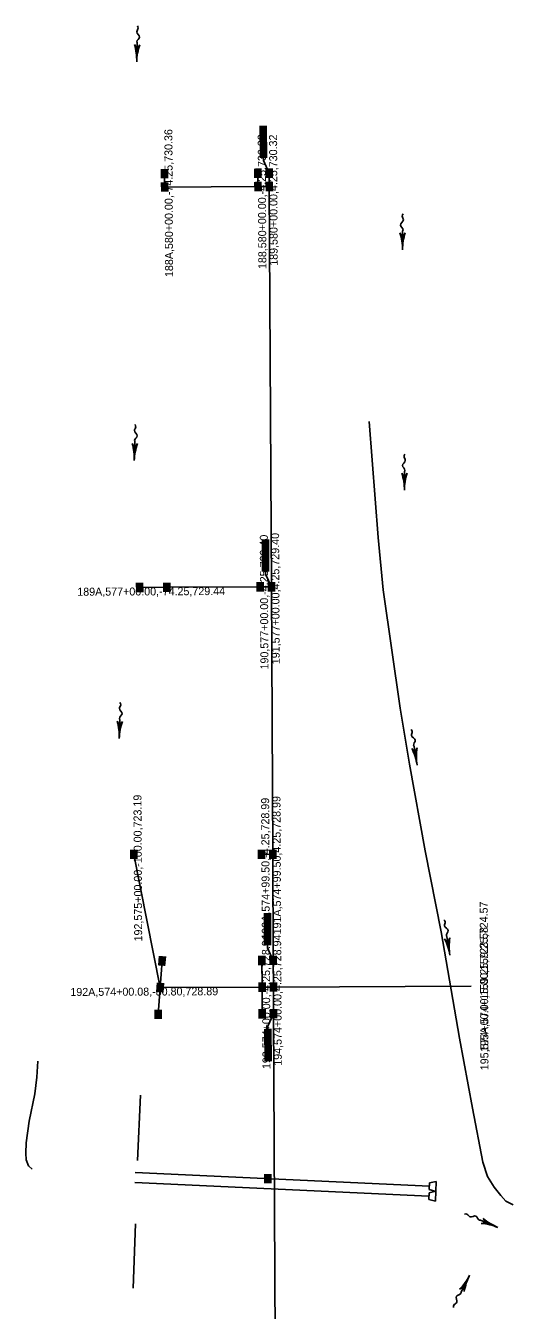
# Model space of a CAD drawing. Extents: x 593481 to 595602, y 151646 to 157396.
# Drawn here: x 594163 to 594529, y 156433 to 157396 of the extents above; entities that cross this region are included whole.
import ezdxf

# ---------------------------------------------------------------- set-up
doc = ezdxf.new("R2010")
doc.units = 0
for name, color, linetype in [('P_ALI_50_Equation', 7, 'Continuous'), ('P_DRN_Flow', 7, 'Continuous'), ('P_DRN_Inlet', 7, 'Continuous'), ('P_DRN_Pipes', 7, 'Continuous'), ('P_DRN_SS_UG', 7, 'Continuous')]:
    doc.layers.add(name, color=color, linetype=linetype)

msp = doc.modelspace()

# ---------------------------------------------------------------- linework, layer by layer
at = {"layer": 'P_DRN_Flow'}
for p, q in [((594246.42, 157368.76), (594246.88, 157382.88)), ((594445.86, 157227.78), (594445.86, 157241.9)), ((594244.64, 157069.85), (594245.1, 157083.97)), ((594447.29, 157047.54), (594447.29, 157061.66)), ((594233.34, 156861.58), (594233.8, 156875.7)), ((594456.75, 156841.63), (594454.55, 156855.59)), ((594481.36, 156699.04), (594479.17, 156713)), ((594517.39, 156495.04), (594504.34, 156500.44)), ((594496.16, 156459.25), (594489.74, 156446.66))]:
    msp.add_line(p, q, dxfattribs=at)
for points in [[(594244.84, 157381.62), (594246.73, 157378.35), (594248.83, 157381.49)], [(594447.87, 157240.57), (594445.87, 157237.37), (594443.87, 157240.58)], [(594243.05, 157082.7), (594244.95, 157079.44), (594247.05, 157082.58)], [(594449.29, 157060.33), (594447.29, 157057.13), (594445.29, 157060.34)], [(594231.75, 156874.43), (594233.65, 156871.17), (594235.75, 156874.31)], [(594452.78, 156853.96), (594455.25, 156851.11), (594456.73, 156854.59)], [(594477.4, 156711.37), (594479.87, 156708.52), (594481.35, 156712)], [(594504.8, 156498.08), (594508.52, 156498.7), (594506.33, 156501.78)], [(594492.13, 156446.94), (594491.8, 156450.7), (594488.56, 156448.76)]]:
    msp.add_lwpolyline(points, dxfattribs=at)
for centre, start, end in [((594204.49, 157370.13), 358.13392, 15.89624), ((594288.36, 157367.4), 160.3716, 178.13392), ((594403.91, 157227.78), 0, 17.76232), ((594487.82, 157227.78), 162.23768, 180), ((594202.7, 157071.21), 358.13392, 15.89624), ((594286.57, 157068.48), 160.3716, 178.13392), ((594405.33, 157047.54), 0, 17.76232), ((594489.25, 157047.54), 162.23768, 180), ((594191.4, 156862.95), 358.13392, 15.89624), ((594275.27, 156860.21), 160.3716, 178.13392), ((594415.3, 156835.11), 8.94535, 26.70767), ((594498.19, 156848.16), 171.18303, 188.94535), ((594439.92, 156692.52), 8.94535, 26.70767), ((594522.81, 156705.57), 171.18303, 188.94535), ((594501.37, 156456.27), 67.5421, 85.30442), ((594533.42, 156533.82), 229.77978, 247.5421), ((594458.79, 156478.33), 315.19309, 332.95541), ((594533.53, 156440.17), 152.95541, 170.71773)]:
    msp.add_arc(centre, 41.96, start, end, dxfattribs=at)
for points in [[(594246.88, 157382.88), (594246.59, 157383.68), (594248.59, 157387.23), (594246.53, 157391.22), (594247.56, 157394.01), (594246.99, 157395.76)], [(594445.86, 157241.9), (594446.18, 157242.69), (594444.29, 157246.3), (594446.49, 157250.22), (594445.55, 157253.05), (594446.18, 157254.78)], [(594245.1, 157083.97), (594244.81, 157084.76), (594246.81, 157088.31), (594244.74, 157092.3), (594245.77, 157095.1), (594245.2, 157096.84)], [(594447.29, 157061.67), (594447.61, 157062.45), (594445.72, 157066.06), (594447.92, 157069.99), (594446.98, 157072.81), (594447.61, 157074.54)], [(594233.8, 156875.7), (594233.51, 156876.5), (594235.51, 156880.04), (594233.44, 156884.04), (594234.47, 156886.83), (594233.9, 156888.58)], [(594454.55, 156855.59), (594454.12, 156856.32), (594455.42, 156860.18), (594452.64, 156863.71), (594453.13, 156866.65), (594452.24, 156868.26)], [(594479.17, 156713), (594478.74, 156713.73), (594480.03, 156717.59), (594477.25, 156721.12), (594477.75, 156724.06), (594476.86, 156725.67)], [(594504.34, 156500.44), (594503.49, 156500.45), (594500.87, 156503.57), (594496.41, 156503.04), (594494.16, 156504.99), (594492.32, 156505.06)], [(594489.74, 156446.66), (594489.66, 156445.82), (594486.34, 156443.46), (594486.51, 156438.97), (594484.39, 156436.88), (594484.16, 156435.06)]]:
    msp.add_spline(points, degree=3, dxfattribs=at)
at = {"layer": 'P_DRN_Inlet'}
for p, q in [((594339.16, 157320.72), (594339.29, 157296.72)), ((594340.06, 157320.72), (594340.19, 157296.72)), ((594340.96, 157320.72), (594341.09, 157296.73)), ((594341.86, 157320.73), (594341.99, 157296.73)), ((594342.76, 157320.73), (594342.89, 157296.73)), ((594343.66, 157320.74), (594343.79, 157296.74)), ((594265.12, 157281.37), (594265.08, 157288.24)), ((594266.02, 157281.37), (594265.98, 157288.25)), ((594266.92, 157281.38), (594266.88, 157288.25)), ((594267.82, 157281.38), (594267.78, 157288.26)), ((594268.72, 157281.38), (594268.68, 157288.26)), ((594269.62, 157281.39), (594269.58, 157288.26)), ((594335.12, 157281.73), (594335.08, 157288.6)), ((594336.02, 157281.73), (594335.98, 157288.61)), ((594336.92, 157281.73), (594336.88, 157288.61)), ((594337.82, 157281.74), (594337.78, 157288.61)), ((594338.72, 157281.74), (594338.68, 157288.62)), ((594339.62, 157281.75), (594339.58, 157288.62)), ((594343.62, 157281.78), (594343.58, 157288.65)), ((594344.52, 157281.78), (594344.48, 157288.66)), ((594345.42, 157281.79), (594345.38, 157288.66)), ((594346.32, 157281.79), (594346.28, 157288.67)), ((594347.22, 157281.8), (594347.18, 157288.67)), ((594348.12, 157281.8), (594348.08, 157288.68)), ((594265.17, 157271.37), (594265.14, 157278.24)), ((594266.07, 157271.37), (594266.04, 157278.25)), ((594266.97, 157271.38), (594266.94, 157278.25)), ((594267.87, 157271.38), (594267.84, 157278.26)), ((594268.77, 157271.38), (594268.74, 157278.26)), ((594269.67, 157271.39), (594269.64, 157278.26)), ((594335.17, 157271.73), (594335.13, 157278.6)), ((594336.07, 157271.73), (594336.03, 157278.61)), ((594336.97, 157271.73), (594336.93, 157278.61)), ((594337.87, 157271.74), (594337.83, 157278.61)), ((594338.77, 157271.74), (594338.73, 157278.62)), ((594339.67, 157271.75), (594339.63, 157278.62)), ((594343.67, 157271.77), (594343.63, 157278.64)), ((594344.57, 157271.77), (594344.53, 157278.65)), ((594345.47, 157271.78), (594345.43, 157278.65)), ((594346.37, 157271.78), (594346.33, 157278.66)), ((594347.27, 157271.79), (594347.23, 157278.66)), ((594348.17, 157271.79), (594348.13, 157278.67)), ((594340.75, 157010.69), (594340.88, 156986.69)), ((594341.65, 157010.7), (594341.78, 156986.7)), ((594342.55, 157010.7), (594342.68, 156986.7)), ((594343.45, 157010.7), (594343.58, 156986.71)), ((594344.35, 157010.71), (594344.48, 156986.71)), ((594345.25, 157010.71), (594345.38, 156986.71)), ((594246.45, 156971.27), (594246.41, 156978.14)), ((594247.35, 156971.27), (594247.31, 156978.15)), ((594248.25, 156971.28), (594248.21, 156978.15)), ((594249.15, 156971.28), (594249.11, 156978.16)), ((594250.05, 156971.28), (594250.01, 156978.16)), ((594250.95, 156971.29), (594250.91, 156978.16)), ((594266.71, 156971.37), (594266.68, 156978.25)), ((594267.61, 156971.37), (594267.58, 156978.25)), ((594268.51, 156971.38), (594268.48, 156978.25)), ((594269.41, 156971.38), (594269.38, 156978.26)), ((594270.31, 156971.39), (594270.28, 156978.26)), ((594271.21, 156971.39), (594271.18, 156978.27)), ((594336.71, 156971.73), (594336.67, 156978.6)), ((594337.61, 156971.73), (594337.57, 156978.61)), ((594338.51, 156971.74), (594338.47, 156978.61)), ((594339.41, 156971.74), (594339.37, 156978.62)), ((594340.31, 156971.75), (594340.27, 156978.62)), ((594341.21, 156971.75), (594341.17, 156978.63)), ((594345.21, 156971.77), (594345.17, 156978.65)), ((594346.11, 156971.78), (594346.07, 156978.65)), ((594347.01, 156971.78), (594346.97, 156978.66)), ((594347.91, 156971.79), (594347.87, 156978.66)), ((594348.81, 156971.79), (594348.77, 156978.67)), ((594349.71, 156971.8), (594349.67, 156978.67)), ((594241.99, 156771.24), (594241.95, 156778.12)), ((594242.89, 156771.25), (594242.85, 156778.12)), ((594243.79, 156771.25), (594243.75, 156778.12)), ((594244.69, 156771.25), (594244.65, 156778.13)), ((594245.59, 156771.26), (594245.55, 156778.13)), ((594246.49, 156771.26), (594246.45, 156778.14)), ((594337.74, 156771.23), (594337.7, 156778.11)), ((594338.64, 156771.24), (594338.6, 156778.11)), ((594339.54, 156771.24), (594339.5, 156778.12)), ((594340.44, 156771.25), (594340.4, 156778.12)), ((594341.34, 156771.25), (594341.3, 156778.13)), ((594342.24, 156771.26), (594342.2, 156778.13)), ((594346.24, 156771.28), (594346.2, 156778.15)), ((594347.14, 156771.28), (594347.1, 156778.16)), ((594348.04, 156771.29), (594348, 156778.16)), ((594348.94, 156771.29), (594348.9, 156778.16)), ((594349.84, 156771.29), (594349.8, 156778.17)), ((594350.74, 156771.3), (594350.7, 156778.17)), ((594342.2, 156730.67), (594342.32, 156706.67)), ((594343.1, 156730.67), (594343.22, 156706.67)), ((594344, 156730.68), (594344.12, 156706.68)), ((594344.9, 156730.68), (594345.02, 156706.68)), ((594345.8, 156730.69), (594345.92, 156706.69)), ((594346.7, 156730.69), (594346.82, 156706.69)), ((594262.92, 156691.57), (594263.44, 156698.43)), ((594263.82, 156691.51), (594264.33, 156698.36)), ((594264.72, 156691.44), (594265.23, 156698.3)), ((594265.62, 156691.37), (594266.13, 156698.23)), ((594266.51, 156691.3), (594267.03, 156698.16)), ((594267.41, 156691.24), (594267.92, 156698.09)), ((594338.15, 156691.73), (594338.11, 156698.61)), ((594339.05, 156691.74), (594339.01, 156698.61)), ((594339.95, 156691.74), (594339.91, 156698.62)), ((594340.85, 156691.75), (594340.81, 156698.62)), ((594341.75, 156691.75), (594341.71, 156698.63)), ((594342.65, 156691.76), (594342.61, 156698.63)), ((594346.65, 156691.79), (594346.61, 156698.66)), ((594347.55, 156691.79), (594347.51, 156698.67)), ((594348.45, 156691.8), (594348.41, 156698.67)), ((594349.35, 156691.8), (594349.31, 156698.68)), ((594350.25, 156691.8), (594350.21, 156698.68)), ((594351.15, 156691.81), (594351.11, 156698.68)), ((594261.43, 156671.61), (594261.94, 156678.46)), ((594262.33, 156671.54), (594262.84, 156678.39)), ((594263.22, 156671.47), (594263.74, 156678.33)), ((594264.12, 156671.4), (594264.63, 156678.26)), ((594265.02, 156671.34), (594265.53, 156678.19)), ((594265.92, 156671.27), (594266.43, 156678.13)), ((594338.25, 156671.73), (594338.21, 156678.61)), ((594339.15, 156671.74), (594339.11, 156678.61)), ((594340.05, 156671.74), (594340.01, 156678.62)), ((594340.95, 156671.75), (594340.91, 156678.62)), ((594341.85, 156671.75), (594341.81, 156678.63)), ((594342.75, 156671.76), (594342.71, 156678.63)), ((594346.75, 156671.78), (594346.71, 156678.65)), ((594347.65, 156671.78), (594347.61, 156678.66)), ((594348.55, 156671.79), (594348.51, 156678.66)), ((594349.45, 156671.79), (594349.41, 156678.67)), ((594350.35, 156671.8), (594350.31, 156678.67)), ((594351.25, 156671.8), (594351.21, 156678.68)), ((594260.35, 156651.33), (594260.32, 156658.21)), ((594261.25, 156651.34), (594261.22, 156658.21)), ((594262.15, 156651.34), (594262.12, 156658.22)), ((594263.05, 156651.35), (594263.02, 156658.22)), ((594263.95, 156651.35), (594263.92, 156658.23)), ((594264.85, 156651.36), (594264.82, 156658.23)), ((594338.35, 156651.73), (594338.32, 156658.61)), ((594339.25, 156651.74), (594339.22, 156658.61)), ((594340.15, 156651.74), (594340.12, 156658.62)), ((594341.05, 156651.75), (594341.02, 156658.62)), ((594341.95, 156651.75), (594341.92, 156658.63)), ((594342.85, 156651.76), (594342.82, 156658.63)), ((594346.85, 156651.79), (594346.82, 156658.66)), ((594347.75, 156651.79), (594347.72, 156658.67)), ((594348.65, 156651.8), (594348.62, 156658.67)), ((594349.55, 156651.8), (594349.52, 156658.67)), ((594350.45, 156651.8), (594350.42, 156658.68)), ((594351.35, 156651.81), (594351.32, 156658.68)), ((594342.64, 156643.79), (594342.76, 156619.79)), ((594343.54, 156643.8), (594343.66, 156619.8)), ((594344.44, 156643.8), (594344.56, 156619.8)), ((594345.34, 156643.8), (594345.46, 156619.81)), ((594346.24, 156643.81), (594346.36, 156619.81)), ((594347.14, 156643.81), (594347.26, 156619.81)), ((594342.57, 156528.19), (594342.53, 156535.07)), ((594343.47, 156528.2), (594343.43, 156535.07)), ((594344.37, 156528.2), (594344.33, 156535.08)), ((594345.27, 156528.21), (594345.23, 156535.08)), ((594346.17, 156528.21), (594346.13, 156535.09)), ((594347.07, 156528.22), (594347.03, 156535.09))]:
    msp.add_line(p, q, dxfattribs=at)
for points in [[(594340.44, 157315.99), (594340.51, 157301.45), (594342.51, 157301.46), (594342.44, 157316)], [(594268.36, 157283.82), (594268.35, 157285.82), (594266.35, 157285.81), (594266.36, 157283.81)], [(594338.36, 157284.18), (594338.35, 157286.18), (594336.35, 157286.17), (594336.36, 157284.17)], [(594346.86, 157284.23), (594346.85, 157286.23), (594344.85, 157286.22), (594344.86, 157284.22)], [(594268.41, 157273.82), (594268.4, 157275.82), (594266.4, 157275.81), (594266.41, 157273.81)], [(594338.41, 157274.18), (594338.4, 157276.18), (594336.4, 157276.17), (594336.41, 157274.17)], [(594346.91, 157274.22), (594346.9, 157276.22), (594344.9, 157276.21), (594344.91, 157274.21)], [(594342.03, 157005.97), (594342.1, 156991.42), (594344.1, 156991.43), (594344.03, 157005.98)], [(594249.68, 156973.72), (594249.67, 156975.72), (594247.67, 156975.71), (594247.68, 156973.71)], [(594269.95, 156973.82), (594269.94, 156975.82), (594267.94, 156975.81), (594267.95, 156973.81)], [(594339.95, 156974.18), (594339.94, 156976.18), (594337.94, 156976.17), (594337.95, 156974.17)], [(594348.45, 156974.23), (594348.44, 156976.23), (594346.44, 156976.22), (594346.45, 156974.22)], [(594245.23, 156773.69), (594245.22, 156775.69), (594243.22, 156775.68), (594243.23, 156773.68)], [(594340.98, 156773.69), (594340.97, 156775.69), (594338.97, 156775.68), (594338.98, 156773.68)], [(594349.48, 156773.73), (594349.47, 156775.73), (594347.47, 156775.72), (594347.48, 156773.72)], [(594343.47, 156725.95), (594343.55, 156711.4), (594345.55, 156711.41), (594345.47, 156725.96)], [(594266.35, 156693.76), (594266.5, 156695.76), (594264.5, 156695.91), (594264.35, 156693.91)], [(594341.38, 156694.19), (594341.37, 156696.19), (594339.37, 156696.18), (594339.38, 156694.18)], [(594349.88, 156694.24), (594349.87, 156696.24), (594347.87, 156696.23), (594347.88, 156694.23)], [(594264.85, 156673.79), (594265, 156675.79), (594263.01, 156675.94), (594262.86, 156673.94)], [(594341.49, 156674.19), (594341.48, 156676.19), (594339.48, 156676.18), (594339.49, 156674.18)], [(594349.99, 156674.23), (594349.98, 156676.23), (594347.98, 156676.22), (594347.99, 156674.22)], [(594263.59, 156653.79), (594263.58, 156655.79), (594261.58, 156655.78), (594261.59, 156653.78)], [(594341.59, 156654.19), (594341.58, 156656.19), (594339.58, 156656.18), (594339.59, 156654.18)], [(594350.09, 156654.24), (594350.08, 156656.24), (594348.08, 156656.23), (594348.09, 156654.23)], [(594343.92, 156639.07), (594343.99, 156624.52), (594345.99, 156624.53), (594345.92, 156639.08)], [(594345.8, 156530.65), (594345.79, 156532.65), (594343.79, 156532.64), (594343.8, 156530.64)]]:
    msp.add_lwpolyline(points, close=True, dxfattribs=at)
at = {"layer": 'P_DRN_Pipes'}
for p, q in [((594245.39, 156536.21), (594465.96, 156526.08)), ((594244.94, 156528.76), (594465.62, 156518.63)), ((594466.08, 156528.58), (594465.85, 156523.58)), ((594465.85, 156523.58), (594470.79, 156522.1)), ((594471.13, 156529.59), (594466.08, 156528.58)), ((594470.79, 156522.1), (594471.13, 156529.59)), ((594465.74, 156521.12), (594465.51, 156516.13)), ((594465.51, 156516.13), (594470.44, 156514.65)), ((594470.79, 156522.14), (594465.74, 156521.12)), ((594470.44, 156514.65), (594470.79, 156522.14))]:
    msp.add_line(p, q, dxfattribs=at)
at = {"layer": 'P_DRN_SS_UG'}
for p, q in [((594267.35, 157284.82), (594267.4, 157274.82)), ((594337.4, 157275.17), (594337.35, 157285.17)), ((594345.85, 157285.23), (594345.9, 157275.22)), ((594267.4, 157274.82), (594337.4, 157275.17)), ((594337.4, 157275.17), (594345.9, 157275.22)), ((594345.9, 157275.22), (594347.44, 156975.22)), ((594268.94, 156974.82), (594338.94, 156975.18)), ((594338.94, 156975.18), (594347.44, 156975.22)), ((594347.44, 156975.22), (594348.47, 156774.72)), ((594248.68, 156974.72), (594268.94, 156974.82)), ((594244.22, 156774.69), (594263.93, 156674.87)), ((594339.97, 156774.68), (594348.47, 156774.72)), ((594348.47, 156774.72), (594348.88, 156695.24)), ((594265.42, 156694.83), (594263.93, 156674.87)), ((594340.48, 156675.18), (594340.38, 156695.18)), ((594348.88, 156695.24), (594348.98, 156675.23)), ((594262.59, 156654.78), (594263.93, 156674.87)), ((594263.93, 156674.87), (594340.48, 156675.18)), ((594340.48, 156675.18), (594348.98, 156675.23)), ((594340.48, 156675.18), (594340.58, 156655.18)), ((594348.98, 156675.23), (594497.36, 156675.99)), ((594349.08, 156655.24), (594348.98, 156675.23)), ((594350.52, 156375.23), (594349.08, 156655.24))]:
    msp.add_line(p, q, dxfattribs=at)
for points in [[(594345.85, 157285.23), (594341.55, 157294.73), (594341.54, 157296.73)], [(594528.92, 156512.09), (594523.22, 156514.81), (594519.47, 156519.07), (594514.44, 156525.15), (594509.64, 156533.2), (594506.08, 156544.08), (594498.37, 156584.35), (594488.59, 156636.93), (594474.73, 156716.61), (594462.78, 156777.43), (594450.93, 156842.33), (594444.05, 156884.21), (594431.21, 156972.86), (594427.45, 157012.21), (594420.91, 157099.06)], [(594347.44, 156975.22), (594343.14, 156984.7), (594343.13, 156986.7)], [(594348.88, 156695.24), (594344.58, 156704.68), (594344.57, 156706.68)], [(594349.08, 156655.24), (594344.88, 156645.8), (594344.89, 156643.8)], [(594168.16, 156538.76), (594165.24, 156541.17), (594163.58, 156545.8), (594163.17, 156550.75), (594163.54, 156558.44), (594165.9, 156574.68), (594169.98, 156595.1), (594171.64, 156607.71), (594172.22, 156619.6)], [(594247.01, 156545.3), (594249.22, 156594.27)], [(594245.47, 156497.73), (594243.85, 156449.49)]]:
    msp.add_lwpolyline(points, dxfattribs=at)

# ---------------------------------------------------------------- texts
at = {"layer": 'P_ALI_50_Equation'}
for s, rotation, p in [('188A,580+00.00,-74.25,730.36', 90.29409, (594273.75, 157207.39)), ('188,580+00.00,-4.25,730.32', 90.29409, (594343.72, 157213.37)), ('189,580+00.00,4.25,730.32', 90.29409, (594352.21, 157215.82)), ('190,577+00.00,-4.25,729.40', 90.29409, (594345.26, 156913.25)), ('191,577+00.00,4.25,729.40', 90.29409, (594353.74, 156917.22)), ('189A,577+00.00,-74.25,729.44', 0.29409, (594201.89, 156968.48)), ('192,575+00.00,-100.00,723.19', 90.29409, (594250.56, 156709.43)), ('190A,574+99.50,-4.25,728.99', 90.29409, (594346.3, 156710.7)), ('191A,574+99.50,4.25,728.99', 90.29409, (594354.78, 156714.67)), ('195A,574+15.00,159.25,724.57', 90.29409, (594510.23, 156626.66)), ('195,574+00.00,159.25,723.58', 90.29409, (594510.3, 156612.89)), ('193,574+00.00,-4.25,728.94', 90.29409, (594346.8, 156613.75)), ('194,574+00.00,4.25,728.94', 90.29409, (594355.28, 156616.25)), ('192A,574+00.08,-80.80,728.89', 0.29409, (594196.69, 156668.52))]:
    msp.add_text(s, height=6, rotation=rotation, dxfattribs=at).set_placement(p)

doc.saveas('drawing.dxf')
